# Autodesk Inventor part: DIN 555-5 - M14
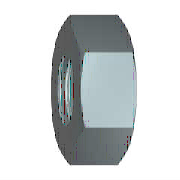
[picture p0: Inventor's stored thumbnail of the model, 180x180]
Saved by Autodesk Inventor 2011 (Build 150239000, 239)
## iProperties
Created: 2010-02
Part Number: DIN 555-5 - M14
Material: Steel, Mild
Description: Hex Nut
Document SubType Name: Modeling
Standard: DIN 555-5
Designer: PC
Standards Organization: DIN
Language: en-US
Size Designation: M14
Categories: <MemberInstance><Categories><Category DisplayName="Fasteners" InternalName="e4da775c-781d-43d5-af7c-5136215cf5a6" Mnemonic="FSTN"><Category DisplayName="Nuts" I
Density: 1 g/cm^3
IsCustomPart: 0
Author: PC
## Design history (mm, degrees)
workaxis "Work Axis1"
workplane "Work Plane1"
sketch "Sketch1"
  geometry: L1 (-12.702, 0)-(-6.351, 11); L2 (-6.351, 11)-(6.351, 11); L3 (6.351, 11)-(12.702, 0); L4 (12.702, 0)-(6.351, -11); L5 (6.351, -11)-(-6.351, -11); L6 (-6.351, -11)-(-12.702, 0); 2 further points
  constraints: 12 end point, 1 coincident, 1 horizontal, 11 other
  dimensions: "d0" = 25.40341 distance of L3.end L1.start (= 1.1547 x SW)
extrude "Body" new body sketch "Sketch1" distance "d1" = 11 (= KOH); taper "d2" = 0 deg
revolve "Chamfer1" stored, may be unused: angle "d7" = 90 deg
sketch "Sketch3"
  geometry: 4 further points
  constraints: 1 coincident, 1 other
hole "Thread" sketch "Sketch3" diameter "d25" = 11.835; stored, may be unused: countersink angle "d29" = 82 deg, drill point angle "d31" = 118 deg; dims "d26" = 6, "d27" = 4, "d28" = 2, "d30" = 8
body "Solid1"
chamfer "Chamfer2" distance "d8" = 1.08253 (= -0.5 x GD1 + 0.5 x NND); stored, may be unused: angle "d9" = 30 deg, second distance "d40" = 1.08253 (= -0.5 x GD1 + 0.5 x NND)
chamfer "Chamfer3" distance "d10" = 1.08253 (= -0.5 x GD1 + 0.5 x NND); stored, may be unused: angle "d11" = 30 deg, second distance "d41" = 1.08253 (= -0.5 x GD1 + 0.5 x NND)
sketch "Sketch2"
  geometry: L1 (0, 6.351)-(0, 12.702) reference; L2 (0, 12.702)-(11, 12.702) reference; L3 (11, 6.351)-(11, 12.702) reference; L4 (-2.2, 0)-(13.2, 0) reference; L5 (1.791, 12.702)-(0, 9.6); L6 (9.209, 12.702)-(11, 9.6)
  constraints: 4 end point, 4 point on line
  dimensions: "d3" = 30 deg angle of L1 L5 (= ANG1); "d4" = 30 deg angle of L3 L6 (= ANG2); "d5" = 19.2 diameter of L5.end L4 (= SW0); "d6" = 19.2 diameter of L6.end L4 (= SW01)
other parameters: "ANG1" = 30 deg [user parameter; used in 1 equation term], "ANG2" = 30 deg [user parameter; used in 1 equation term], "NND" = 14 [user parameter; used in 4 equation terms], "KOH" = 11 [user parameter; used in 1 equation term], "SW" = 22 [user parameter; used in 2 equation terms], "SW0" = 19.2 [user parameter; used in 1 equation term], "SW01" = 19.2 [user parameter; used in 1 equation term], "GD1" = 11.83494 (computed from THREADDIA, PTC, TOA) [user parameter; used in 4 equation terms], "d13" = 0, "d14" = 0, "d39" = 0, "d42" = 0, "GUL" = 1.08253 (= 0.541266 x PTC) [user parameter], "TPU" = 5 (computed from PTC) [user parameter], "THREADDIA" = 14 [user parameter; used in 1 equation term], "TOA" = 30 deg [user parameter; used in 1 equation term], "PTC" = 2 [user parameter; used in 4 equation terms], "E0" = 25.41 (= 1.155 x SW) [user parameter], "GAL" = 1.08253 (= 0.541266 x PTC) [user parameter]
